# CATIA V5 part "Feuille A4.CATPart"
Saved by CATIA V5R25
Part number: Feuille A4
Bounding box of the stored display mesh (mm): x -148.5 to 148.5, y -105 to 105, z 0 to 1
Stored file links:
  C:\Users\m000605\Desktop\Projet FAB liseuse\Feuille A4.CATPart
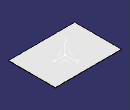
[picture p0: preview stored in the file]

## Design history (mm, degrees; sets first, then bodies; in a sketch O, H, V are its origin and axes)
AxisSystem1: origin (0, 0, 0), X (1, 0, 0), Y (0, 1, 0), Z (0, 0, 1)
Set1
  Sketch1 on XY plane of AxisSystem1, origin (0, 0, 0), H (1, 0, 0), V (0, 1, 0)
    line L1 (-148.5, 105) -> (148.5, 105)
    line L2 (148.5, 105) -> (148.5, -105)
    line L3 (148.5, -105) -> (-148.5, -105)
    line L4 (-148.5, -105) -> (-148.5, 105)
    length L1 = 297
    length L2 = 210
    horizontal: L1 H, L3 H
    vertical: L2 V, L4 V
    symmetry: L4 L2 V, L1 L3 H
Body1 (main body)
  Pad1: profile Sketch1, direction (0, 0, 1), length 1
